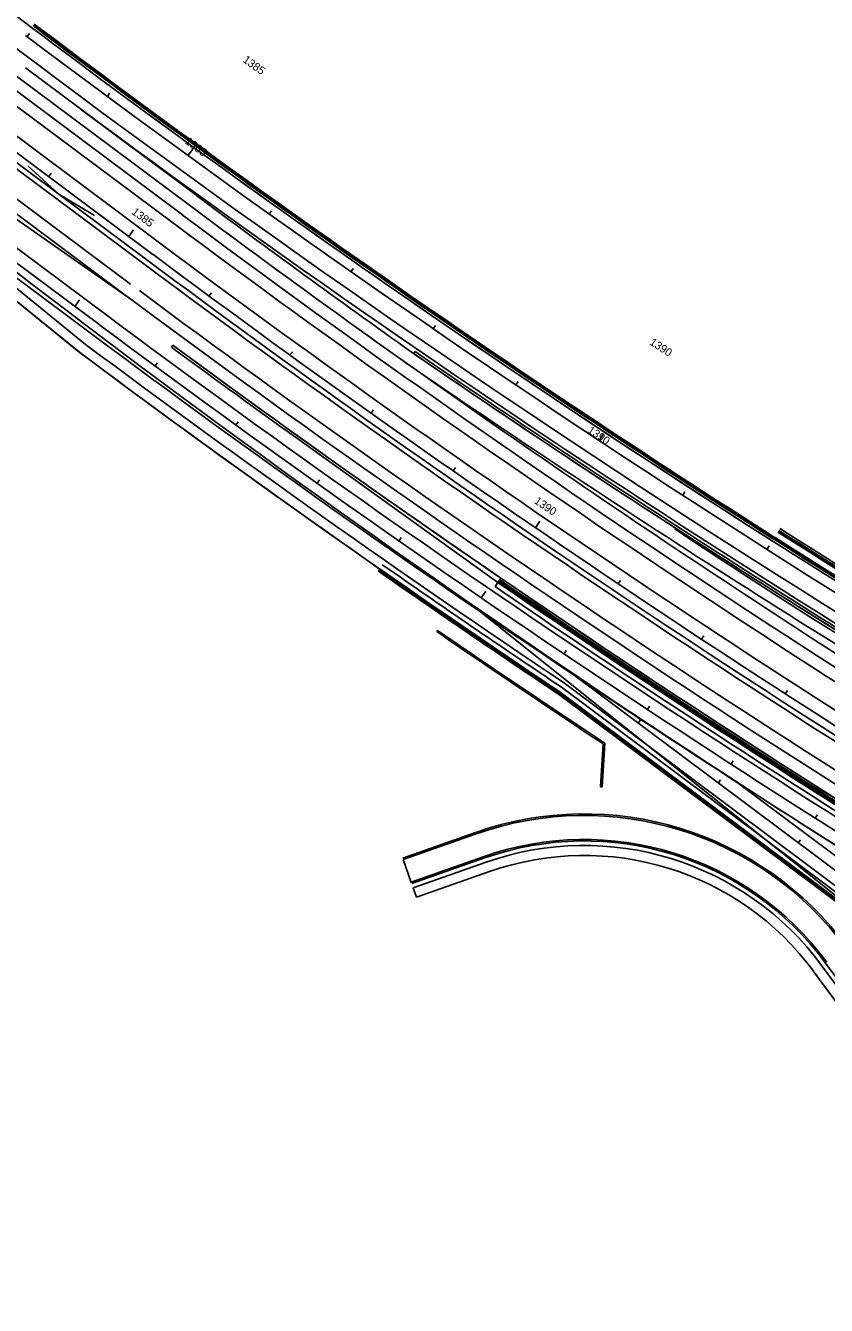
# Model space of a CAD drawing. Extents: x 2339272 to 2351734, y 366540 to 375057.
# Drawn here: x 2345172 to 2345972, y 369492 to 370772 of the extents above; entities that cross this region are included whole.
import ezdxf

# ---------------------------------------------------------------- set-up
doc = ezdxf.new("R2010")
doc.units = 0
for name, color, linetype in [('RD_HC_Cl', 7, 'Continuous'), ('RD_HC_CL_Rel', 7, 'Continuous'), ('RD_HC_Data_Tic', 7, 'Continuous'), ('RD_HC_Data_Tic_Rel', 7, 'Continuous'), ('RD_HC_TX_Rel_Sta50', 7, 'Continuous'), ('RD_HC_TX_Sta50', 7, 'Continuous'), ('RD_PD_Final_LnLine', 7, 'Continuous'), ('RD_PD_Final_TrvlWay', 7, 'Continuous'), ('RD_PD_FOC', 7, 'Continuous'), ('RD_PD_GR', 7, 'Continuous'), ('RD_PD_MedBWall', 7, 'Continuous'), ('RD_PD_MedGR', 7, 'Continuous'), ('RD_PD_NOISE-WALL-GM', 7, 'Continuous'), ('RD_PD_PaveShd', 7, 'Continuous'), ('RD_PD_SW', 7, 'Continuous'), ('RD_PD_WallFill', 7, 'Continuous')]:
    doc.layers.add(name, color=color, linetype=linetype)

msp = doc.modelspace()

# ---------------------------------------------------------------- linework, layer by layer
at = {"layer": 'RD_HC_Cl'}
for p, q in [((2339299.7, 375020.3), (2345298.7, 370542.8)), ((2345614.6, 370194.7), (2346103.4, 369803.5)), ((2345614.6, 370194.7), (2346103.4, 369803.5)), ((2345614.6, 370194.7), (2346103.4, 369803.5)), ((2345614.6, 370194.7), (2346103.4, 369803.5)), ((2345717.1, 370123.9), (2346548.7, 369501.6))]:
    msp.add_line(p, q, dxfattribs=at)
for centre, radius, start, end in [((2352034, 379865.6), 11400.7, 232.99132, 241.72492), ((2352152.8, 379726.2), 11459.2, 233.26372, 239.17851), ((2349158.4, 375253.9), 6000, 236.19528, 241.60251), ((2349158.4, 375253.9), 6000, 236.19528, 241.60251), ((2349158.4, 375253.9), 6000, 236.19528, 241.60251), ((2349158.4, 375253.9), 6000, 236.19528, 241.60251)]:
    msp.add_arc(centre, radius, start, end, dxfattribs=at)
at = {"layer": 'RD_HC_CL_Rel'}
msp.add_line((2345022, 370639), (2345245.9, 370472), dxfattribs=at)
msp.add_arc((2352152.8, 379726.2), 11547.6, 233.26372, 239.17851, dxfattribs=at)
at = {"layer": 'RD_HC_Data_Tic'}
for p, q in [((2345173, 370760.5), (2345175.4, 370763.7)), ((2345253.2, 370700.7), (2345255.5, 370703.9)), ((2345333.8, 370641.6), (2345338.5, 370648)), ((2345194.6, 370620.6), (2345196.9, 370623.8)), ((2345415, 370583.1), (2345417.3, 370586.4)), ((2345274.7, 370560.8), (2345279.5, 370567.2)), ((2345496.6, 370525.4), (2345498.9, 370528.7)), ((2345355, 370501.2), (2345357.3, 370504.4)), ((2345578.8, 370468.5), (2345581.1, 370471.8)), ((2345435.7, 370442.2), (2345438.1, 370445.4)), ((2345661.5, 370412.2), (2345663.7, 370415.5)), ((2345517, 370383.9), (2345519.3, 370387.2)), ((2345744.7, 370356.7), (2345749.1, 370363.3)), ((2345598.8, 370326.4), (2345601.1, 370329.7)), ((2345828.3, 370301.9), (2345830.5, 370305.2)), ((2345681, 370269.5), (2345685.6, 370276.1)), ((2345912.4, 370247.8), (2345914.6, 370251.2)), ((2345763.8, 370213.4), (2345766, 370216.7)), ((2345847.1, 370158), (2345849.3, 370161.4)), ((2345930.8, 370103.4), (2345933, 370106.7)), ((2345783.6, 370074.1), (2345786, 370077.3)), ((2345863.6, 370014.2), (2345866, 370017.4)), ((2345943.7, 369954.3), (2345946.1, 369957.5))]:
    msp.add_line(p, q, dxfattribs=at)
at = {"layer": 'RD_HC_Data_Tic_Rel'}
for p, q in [((2345220.6, 370490.8), (2345225.4, 370497.2)), ((2345300.9, 370431.2), (2345303.3, 370434.4)), ((2345381.7, 370372.2), (2345384, 370375.4)), ((2345462.9, 370313.9), (2345465.2, 370317.2)), ((2345544.7, 370256.3), (2345547, 370259.6)), ((2345626.9, 370199.4), (2345631.4, 370206)), ((2345709.7, 370143.3), (2345711.9, 370146.6)), ((2345792.9, 370087.8), (2345795.1, 370091.2)), ((2345876.6, 370033.1), (2345878.8, 370036.5)), ((2345960.8, 369979.1), (2345962.9, 369982.5))]:
    msp.add_line(p, q, dxfattribs=at)
at = {"layer": 'RD_PD_Final_LnLine'}
for p, q in [((2344195, 371413), (2345321, 370572.6)), ((2344150.5, 371353.5), (2345276.5, 370513.1)), ((2344782.9, 370989.2), (2345328.2, 370582.3)), ((2345022, 370639), (2345245.9, 370472)), ((2345014.9, 370629.4), (2345238.7, 370462.4)), ((2345717.1, 370123.9), (2346548.7, 369501.6)), ((2345549, 369937.7), (2345621.8, 369963.3)), ((2345557, 369915.1), (2345629.8, 369940.7))]:
    msp.add_line(p, q, dxfattribs=at)
for centre, radius, start, end in [((2351872.8, 379241), 11000, 231.26372, 239.17851), ((2351872.8, 379241), 11000, 231.26372, 239.17851), ((2351872.8, 379241), 11000, 231.26372, 239.17851), ((2351872.8, 379241), 11000, 231.26372, 239.17851), ((2352152.8, 379726.2), 11410, 233.26372, 239.17851), ((2352152.8, 379726.2), 11422, 233.26372, 239.17851), ((2352152.8, 379726.2), 11496.3, 233.31776, 239.17851), ((2352152.8, 379726.2), 11547.6, 233.26372, 239.17851), ((2352152.8, 379726.2), 11559.6, 233.26372, 236.16882), ((2352152.8, 379726.2), 11398, 234.59863, 238.49864), ((2352152.8, 379726.2), 11559.6, 236.16882, 237.15193), ((2345729.7, 369656.8), 325, 36.3291, 109.3829), ((2345729.7, 369656.8), 301, 36.3291, 109.3829)]:
    msp.add_arc(centre, radius, start, end, dxfattribs=at)
at = {"layer": 'RD_PD_Final_TrvlWay'}
for p, q in [((2344605.8, 370998.7), (2345269.3, 370503.4)), ((2344790.4, 370998.6), (2345335.3, 370591.9)), ((2345278, 370497), (2344958.3, 370720.6)), ((2345231.5, 370452.8), (2345014.5, 370628.6)), ((2345129.3, 370574), (2345253, 370481.6)), ((2345710.1, 370114.1), (2346541.5, 369491.9)), ((2345882.8, 370014.8), (2346297.7, 369704.4)), ((2345556.9, 369914.9), (2345549, 369937.7))]:
    msp.add_line(p, q, dxfattribs=at)
for centre, radius, start, end in [((2352034, 379865.6), 11400.7, 232.99132, 241.72492), ((2352034, 379865.6), 11416.7, 232.99132, 241.72492), ((2352152.8, 379726.2), 11398, 233.26372, 234.59863), ((2352152.8, 379726.2), 11508.3, 233.26372, 239.17851), ((2352152.8, 379726.2), 11535.6, 233.26372, 239.17851), ((2352152.8, 379726.2), 11571.6, 233.26372, 236.16727), ((2352001.8, 379817.3), 11386.2, 235.48365, 239.38613), ((2352152.8, 379726.2), 11559.6, 237.15193, 239.17851)]:
    msp.add_arc(centre, radius, start, end, dxfattribs=at)
at = {"layer": 'RD_PD_FOC'}
for p, q in [((2345548.5, 369939.1), (2345621.3, 369964.8)), ((2345557.5, 369913.7), (2345630.3, 369939.3)), ((2345971, 369834.2), (2346115.9, 369637))]:
    msp.add_line(p, q, dxfattribs=at)
for radius in [326.5, 299.5]:
    msp.add_arc((2345729.7, 369656.8), radius, 36.3291, 109.3829, dxfattribs=at)
at = {"layer": 'RD_PD_GR'}
msp.add_line((2345225.2, 370445), (2345008.2, 370620.9), dxfattribs=at)
msp.add_arc((2352152.8, 379726.2), 11581.6, 233.26372, 235.09228, dxfattribs=at)
at = {"layer": 'RD_PD_MedBWall'}
for p, q in [((2344819.2, 371039.8), (2345177.5, 370769.6)), ((2345318.7, 370451.9), (2345317.3, 370450)), ((2345560.7, 370445.5), (2345559.4, 370443.6)), ((2345432.9, 370365.9), (2345643.5, 370214.7)), ((2345640.7, 370210.6), (2345643.5, 370214.7)), ((2345644.9, 370216.7), (2345643.5, 370214.7)), ((2345643.5, 370214.7), (2345644.1, 370215.6)), ((2345645.2, 370217.1), (2345646.5, 370219.1)), ((2345703.8, 370105.1), (2346289, 369667.1)), ((2345703.8, 370105.1), (2346273, 369679.1)), ((2345704.4, 370105.9), (2346273.6, 369679.9)), ((2346289.6, 369667.9), (2345704.4, 370105.9)), ((2346276.6, 369683.9), (2345707.2, 370110))]:
    msp.add_line(p, q, dxfattribs=at)
for centre, radius, start, end in [((2352034, 379865.6), 11390.7, 232.99132, 237.52398), ((2352034, 379865.6), 11388.4, 232.99132, 237.52398), ((2352152.8, 379726.2), 11522.7, 233.61364, 234.32461), ((2352152.8, 379726.2), 11520.3, 233.61364, 235.61367), ((2352002, 379817.2), 11371.8, 235.499, 239.0438), ((2352002, 379817.2), 11374.2, 235.499, 239.0438), ((2352034, 379865.6), 11378.2, 237.52318, 241.72492), ((2352034, 379865.6), 11376.2, 237.52318, 241.72492), ((2352034, 379865.6), 11390.7, 237.52318, 240.43629), ((2352034, 379865.6), 11388.4, 237.52318, 240.43629), ((2352152.8, 379726.2), 11581.6, 235.09228, 236.16599), ((2352152.8, 379726.2), 11576.6, 235.09228, 236.16663), ((2352152.8, 379726.2), 11525.6, 235.61364, 239.17851), ((2352152.8, 379726.2), 11524.6, 235.61364, 239.17851), ((2352152.8, 379726.2), 11522.3, 235.61364, 239.17851), ((2352152.8, 379726.2), 11520.3, 235.61364, 239.17851), ((2352152.8, 379726.2), 11530.6, 235.61364, 239.17851)]:
    msp.add_arc(centre, radius, start, end, dxfattribs=at)
at = {"layer": 'RD_PD_MedGR'}
for p, q in [((2343635.7, 371774.1), (2345204.8, 370603)), ((2345173.6, 370631.3), (2345204.8, 370603)), ((2345204.8, 370603), (2345240.2, 370581.6)), ((2345204.8, 370603), (2345294, 370536.4))]:
    msp.add_line(p, q, dxfattribs=at)
msp.add_arc((2352152.8, 379726.2), 11467.2, 233.26372, 238.61364, dxfattribs=at)
at = {"layer": 'RD_PD_NOISE-WALL-GM'}
for p, q in [((2345583.3, 370166.8), (2345582.5, 370165.6)), ((2345582.5, 370165.6), (2345590.7, 370159.9)), ((2345583.3, 370166.8), (2345591.6, 370161.1)), ((2345748.9, 370053.3), (2345746.2, 370010.5)), ((2345747.7, 370010.4), (2345750.4, 370054.1)), ((2345746.2, 370010.5), (2345747.7, 370010.4))]:
    msp.add_line(p, q, dxfattribs=at)
for centre, radius, start, end in [((2352034, 379865.6), 11387.9, 232.99132, 237.52398), ((2352034, 379865.6), 11386.4, 232.99132, 237.52398), ((2352034, 379865.6), 11387.9, 237.52318, 240.53856), ((2352034, 379865.6), 11386.4, 237.52318, 240.53856), ((2352152.8, 379726.2), 11600.7, 235.55123, 236.49314), ((2352152.8, 379726.2), 11599.2, 235.55122, 236.49742)]:
    msp.add_arc(centre, radius, start, end, dxfattribs=at)
at = {"layer": 'RD_PD_PaveShd'}
for p, q in [((2343761.9, 371706.3), (2345306.6, 370553.4)), ((2343847.6, 371609.5), (2345290.9, 370532.3)), ((2344819.2, 371039.8), (2345177.5, 370769.6)), ((2345227.3, 370687.4), (2345342.5, 370601.5)), ((2345225.4, 370444.9), (2344991, 370634.8)), ((2345432.9, 370365.9), (2345643.5, 370214.7)), ((2345704.4, 370105.9), (2346273.6, 369679.9))]:
    msp.add_line(p, q, dxfattribs=at)
for centre, radius, start, end in [((2352034, 379865.6), 11390.7, 232.99132, 237.52318), ((2352034, 379865.6), 11426.7, 233.08852, 240.43661), ((2352152.8, 379726.2), 11386, 233.26372, 234.59863), ((2352152.8, 379726.2), 11446, 233.26372, 239.17851), ((2352152.8, 379726.2), 11472.3, 233.26372, 239.17851), ((2352152.8, 379726.2), 11520.3, 233.61364, 239.17851), ((2352002, 379817.2), 11374.2, 235.48286, 239.0438), ((2352152.8, 379726.2), 11581.6, 233.26273, 236.16599)]:
    msp.add_arc(centre, radius, start, end, dxfattribs=at)
at = {"layer": 'RD_PD_SW'}
for p, q in [((2345558.9, 369909.4), (2345631.8, 369935)), ((2345562.3, 369900), (2345635.1, 369925.6)), ((2345558.9, 369909.4), (2345562.3, 369900)), ((2345967.4, 369831.5), (2346112.3, 369634.4)), ((2345959.3, 369825.6), (2346104.3, 369628.5))]:
    msp.add_line(p, q, dxfattribs=at)
for radius in [295, 285]:
    msp.add_arc((2345729.7, 369656.8), radius, 36.3291, 109.3829, dxfattribs=at)
at = {"layer": 'RD_PD_WallFill'}
for p, q in [((2345645, 370216.8), (2345644.1, 370215.6)), ((2345702.9, 370103.9), (2346294.9, 369660.9)), ((2346294.9, 369660.9), (2345702.9, 370103.9)), ((2346294.8, 369661.6), (2345703.2, 370104.3)), ((2346294.7, 369662.3), (2345703.5, 370104.7)), ((2345703.8, 370105.1), (2346294.6, 369663)), ((2345703.8, 370105.1), (2346294.6, 369663)), ((2345703.8, 370105.1), (2346294.6, 369663))]:
    msp.add_line(p, q, dxfattribs=at)
for centre, radius, start, end in [((2352034, 379865.6), 11379.2, 237.52318, 240.57884), ((2352034, 379865.6), 11378.7, 237.52318, 240.58136), ((2352034, 379865.6), 11380.2, 237.52318, 240.5738), ((2352034, 379865.6), 11379.7, 237.52318, 240.57632), ((2352152.8, 379726.2), 11582.6, 235.09228, 236.16599), ((2352152.8, 379726.2), 11584.1, 235.09228, 236.16599), ((2352152.8, 379726.2), 11583.6, 235.09228, 236.16599), ((2352152.8, 379726.2), 11583.1, 235.09228, 236.16599), ((2352152.8, 379726.2), 11524.6, 235.61364, 239.17851), ((2352152.8, 379726.2), 11524.1, 235.61364, 239.17851), ((2352152.8, 379726.2), 11523.6, 235.61364, 239.17851), ((2352152.8, 379726.2), 11523.1, 235.61364, 239.17851)]:
    msp.add_arc(centre, radius, start, end, dxfattribs=at)

# ---------------------------------------------------------------- texts
at = {"layer": 'RD_HC_TX_Rel_Sta50'}
for s, rotation, p in [('1385', 323.2637, (2345276.7, 370583.8)), ('1390', 325.5885, (2345679.1, 370294.6))]:
    msp.add_text(s, height=8, rotation=rotation, dxfattribs=at).set_placement(p)
at = {"layer": 'RD_HC_TX_Sta50'}
for s, rotation, p in [('1385', 324.006, (2345387.9, 370735.8)), ('1385', 323.2637, (2345330, 370654.3)), ('1390', 326.5189, (2345794.5, 370453.2)), ('1390', 325.6136, (2345732.4, 370365.3))]:
    msp.add_text(s, height=8, rotation=rotation, dxfattribs=at).set_placement(p)

doc.saveas('drawing.dxf')
